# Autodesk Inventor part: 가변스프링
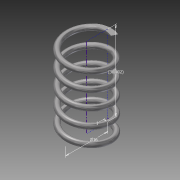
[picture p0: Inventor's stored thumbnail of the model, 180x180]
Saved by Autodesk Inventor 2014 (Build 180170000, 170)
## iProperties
Created: 2016-12
Part Number: 가변스프링
Material: Stainless Steel
Document SubType Name: Modeling
Designer: user
Density: 8.08 g/cm^3
Appearance: Semi-Polished
Mass: 6.37471 g
Surface Area: 16.0182 cm^2
Volume: 0.788949 cm^3
Author: user
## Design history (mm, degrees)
sketch "Sketch1"
  geometry: L1 (0, 0)-(8, 0); L2 (8, 0)-(8, 30.402); L3 (8, 30.402)-(0, 30.402); L4 (0, 30.402)-(0, 0); C1 r 1 at (8, 0)
  constraints: 8 end point, 2 parallel, 1 centre point, 1 coincident, 1 horizontal, 1 perpendicular
  dimensions: "d0" = 16 diameter of L2 L4; "d1" = 30.40208 distance between parallel lines of L1 L3 (derived); "d2" = 1 radius of C1
coil "Coil1" pitch "d3" = 6; turns "d5" = 1; dims "d4" = 30.40208 (= d1), "d6" = 0, angle "d7" = 90 deg, angle "d8" = 90 deg, "d9" = 0, "d10" = 0
sketch "Sketch2"
  geometry: L1 (0, 7)-(0, 9) reference; 1 further point
  constraints: 1 vertical alignment
extrude "Extrusion1" cut sketch "Sketch2" distance "d11" = 10; taper "d12" = 0 deg
workplane "Work Plane1"
workplane "Work Plane2"
sketch "Sketch3"
  geometry: L1 (-2.861, 6.389)-(-3.679, 8.214) reference; 1 further point
  constraints: 1 other
extrude "Extrusion2" cut sketch "Sketch3" distance "d13" = 10; taper "d14" = 0 deg
body "Solid1"
node "Project Cut Edges1"
node "Project Cut Edges2"
